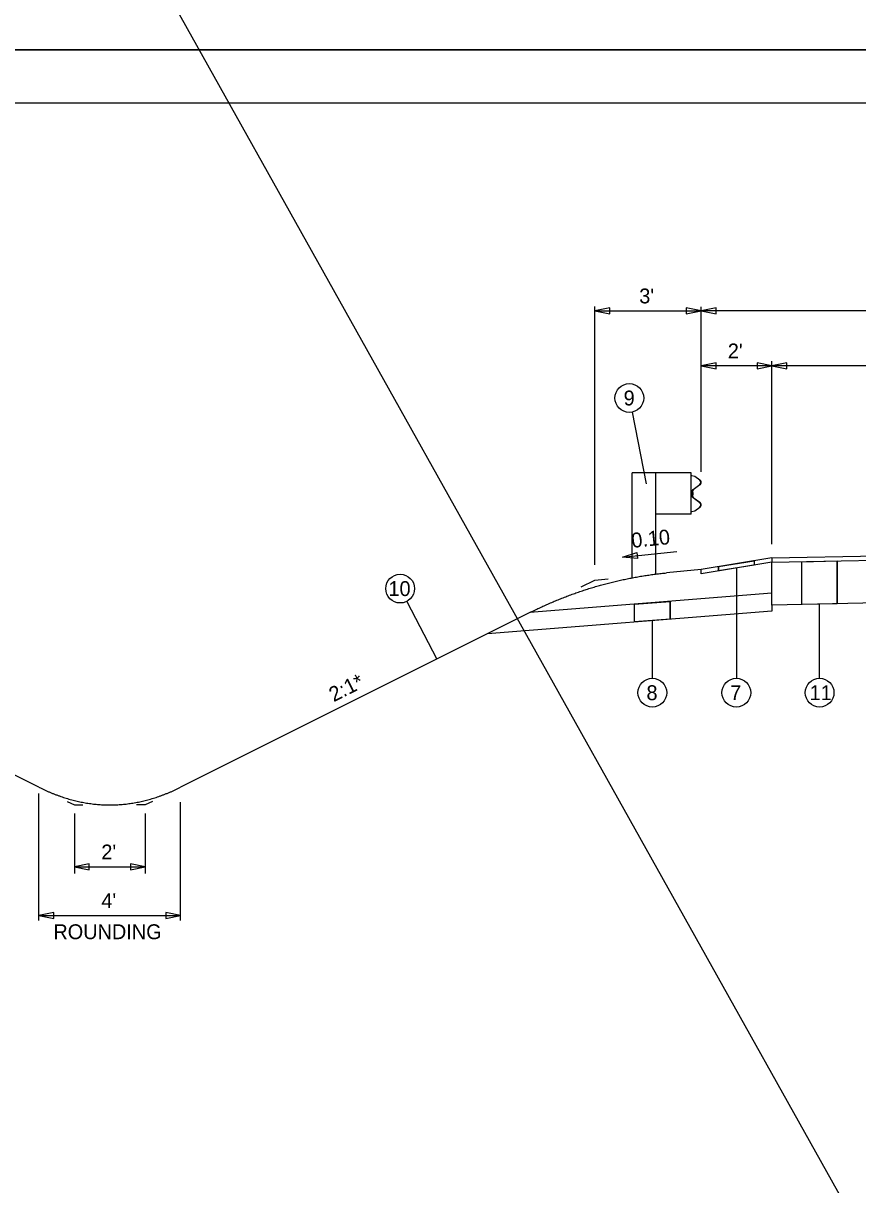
# Model space of a CAD drawing. Extents: x -396 to 156, y -166 to 172.
# Drawn here: x -342.79 to -319.23, y 35.47 to 68.25 of the extents above; entities that cross this region are included whole.
import ezdxf

# ---------------------------------------------------------------- set-up
doc = ezdxf.new("R2010")
doc.units = 0
for name, color, linetype in [('MT_P_Temp_Road', 7, 'Continuous'), ('RD_P_Cells', 7, 'Continuous'), ('SH_Border', 7, 'Continuous'), ('SH_Cut_Line', 7, 'Continuous'), ('TX_P_1', 7, 'Continuous'), ('TX_X_1', 7, 'Continuous'), ('XS_P_Finished_Grade', 7, 'Continuous'), ('XS_P_Pavt_Surface', 7, 'Continuous')]:
    doc.layers.add(name, color=color, linetype=linetype)

msp = doc.modelspace()

# ---------------------------------------------------------------- linework, layer by layer
at = {"layer": 'MT_P_Temp_Road'}
for p, q in [((-321.652, 51.829), (-321.652, 53.037)), ((-318.652, 51.891), (-321.652, 51.829))]:
    msp.add_line(p, q, dxfattribs=at)
at = {"layer": 'RD_P_Cells'}
for p, q in [((-324.933, 55.559), (-325.6, 55.559)), ((-325.6, 52.599), (-325.6, 55.559)), ((-323.933, 55.559), (-324.933, 55.559)), ((-324.933, 52.705), (-324.933, 55.559)), ((-323.933, 54.392), (-323.933, 55.559)), ((-323.918, 55.487), (-323.918, 55.487)), ((-323.918, 55.487), (-323.831, 55.472)), ((-323.918, 55.477), (-323.918, 55.487)), ((-323.918, 55.477), (-323.918, 55.477)), ((-323.835, 55.463), (-323.918, 55.477)), ((-323.835, 55.463), (-323.835, 55.463)), ((-323.693, 55.357), (-323.835, 55.463)), ((-323.831, 55.472), (-323.831, 55.472)), ((-323.831, 55.472), (-323.687, 55.365)), ((-323.813, 55.447), (-323.813, 55.447)), ((-323.807, 55.455), (-323.807, 55.455)), ((-323.881, 55.093), (-323.694, 55.231)), ((-323.881, 55.093), (-323.881, 55.093)), ((-323.688, 55.223), (-323.875, 55.085)), ((-323.814, 55.142), (-323.814, 55.142)), ((-323.808, 55.135), (-323.808, 55.135)), ((-323.694, 55.231), (-323.694, 55.231)), ((-323.693, 55.357), (-323.693, 55.357)), ((-323.688, 55.223), (-323.688, 55.223)), ((-323.687, 55.365), (-323.687, 55.365)), ((-323.662, 55.294), (-323.662, 55.294)), ((-323.652, 55.294), (-323.652, 55.294)), ((-323.917, 55.021), (-323.917, 55.021)), ((-323.917, 54.93), (-323.917, 55.021)), ((-323.917, 54.944), (-323.917, 55.007)), ((-323.917, 54.93), (-323.917, 54.93)), ((-323.907, 55.021), (-323.907, 55.021)), ((-323.907, 55.021), (-323.907, 54.93)), ((-323.907, 54.944), (-323.907, 55.007)), ((-323.907, 54.93), (-323.907, 54.93)), ((-323.881, 54.858), (-323.881, 54.858)), ((-323.693, 54.721), (-323.881, 54.858)), ((-323.875, 55.085), (-323.875, 55.085)), ((-323.875, 54.866), (-323.875, 54.866)), ((-323.875, 54.866), (-323.687, 54.729)), ((-323.916, 54.474), (-323.833, 54.489)), ((-323.829, 54.479), (-323.916, 54.464)), ((-323.916, 54.474), (-323.916, 54.474)), ((-323.916, 54.464), (-323.916, 54.474)), ((-323.916, 54.464), (-323.916, 54.464)), ((-323.833, 54.489), (-323.692, 54.595)), ((-323.686, 54.587), (-323.829, 54.479)), ((-323.693, 54.721), (-323.693, 54.721)), ((-323.692, 54.595), (-323.692, 54.595)), ((-323.687, 54.729), (-323.687, 54.729)), ((-323.686, 54.587), (-323.686, 54.587)), ((-323.661, 54.658), (-323.661, 54.658)), ((-323.651, 54.658), (-323.651, 54.658)), ((-323.933, 54.392), (-324.933, 54.392))]:
    msp.add_line(p, q, dxfattribs=at)
for points in [[(-323.899, 55.036), (-323.899, 54.916), (-323.907, 54.916), (-323.907, 55.036)], [(-323.899, 55.004), (-323.899, 54.946), (-323.874, 54.946), (-323.874, 55.004)]]:
    msp.add_lwpolyline(points, close=True, dxfattribs=at)
for centre, radius, start, end in [((-323.829, 55.022), 0.0886, 126.318, 180.0944), ((-323.741, 55.294), 0.0787, 306.318, 53.2212), ((-323.741, 55.294), 0.0886, 306.318, 53.2212), ((-323.828, 54.93), 0.0886, 180.0944, 233.8707), ((-323.829, 55.022), 0.0788, 126.318, 180.0944), ((-323.828, 54.93), 0.0788, 180.0944, 233.8707), ((-323.739, 54.658), 0.0787, 306.9675, 53.8707), ((-323.739, 54.658), 0.0886, 306.9675, 53.8707)]:
    msp.add_arc(centre, radius, start, end, dxfattribs=at)
at = {"layer": 'SH_Border'}
msp.add_lwpolyline([(-354.402, 66.004), (-258.402, 66.004), (-258.402, 3.004), (-354.402, 3.004)], close=True, dxfattribs=at)
at = {"layer": 'SH_Cut_Line'}
for points in [[(-358.902, 67.504), (-256.902, 67.504), (-256.902, 133.504), (-358.902, 133.504)], [(-358.902, 1.504), (-256.902, 1.504), (-256.902, 67.504), (-358.902, 67.504)]]:
    msp.add_lwpolyline(points, close=True, dxfattribs=at)
at = {"layer": 'TX_P_1'}
for p, q in [((-326.652, 52.968), (-326.652, 60.256)), ((-326.652, 60.136), (-323.652, 60.136)), ((-326.232, 60.052), (-326.232, 60.22)), ((-324.072, 60.22), (-324.072, 60.052)), ((-323.652, 55.588), (-323.652, 60.247)), ((-308.652, 60.136), (-323.652, 60.136)), ((-323.232, 60.052), (-323.232, 60.22)), ((-321.652, 53.553), (-321.652, 58.712)), ((-321.652, 58.583), (-323.652, 58.583)), ((-323.232, 58.499), (-323.232, 58.667)), ((-322.072, 58.667), (-322.072, 58.499)), ((-308.652, 58.583), (-321.652, 58.583)), ((-321.232, 58.499), (-321.232, 58.667)), ((-325.878, 53.186), (-324.343, 53.339)), ((-325.468, 53.311), (-325.452, 53.144)), ((-321.652, 52.164), (-328.493, 51.616)), ((-321.652, 51.829), (-321.652, 51.662)), ((-321.652, 51.662), (-329.688, 51.019)), ((-342.35, 42.924), (-342.35, 46.509)), ((-338.35, 42.924), (-338.35, 46.265)), ((-341.35, 45.95), (-341.35, 44.25)), ((-339.35, 45.95), (-339.35, 44.25)), ((-341.35, 44.44), (-339.35, 44.44)), ((-340.93, 44.356), (-340.93, 44.524)), ((-339.77, 44.524), (-339.77, 44.356)), ((-342.35, 43.064), (-338.35, 43.064)), ((-341.93, 42.98), (-341.93, 43.148)), ((-338.77, 43.148), (-338.77, 42.98))]:
    msp.add_line(p, q, dxfattribs=at)
for points in [[(-326.232, 60.22), (-326.652, 60.136), (-326.232, 60.052)], [(-324.072, 60.052), (-323.652, 60.136), (-324.072, 60.22)], [(-323.232, 60.22), (-323.652, 60.136), (-323.232, 60.052)], [(-323.232, 58.667), (-323.652, 58.583), (-323.232, 58.499)], [(-322.072, 58.499), (-321.652, 58.583), (-322.072, 58.667)], [(-321.232, 58.667), (-321.652, 58.583), (-321.232, 58.499)], [(-325.452, 53.144), (-325.878, 53.186), (-325.468, 53.311)], [(-327.042, 52.342), (-326.652, 52.537), (-326.277, 52.575)], [(-341.553, 46.289), (-341.35, 46.188), (-341.108, 46.188)], [(-339.148, 46.289), (-339.35, 46.188), (-339.593, 46.188)], [(-340.93, 44.524), (-341.35, 44.44), (-340.93, 44.356)], [(-339.77, 44.356), (-339.35, 44.44), (-339.77, 44.524)], [(-341.93, 43.148), (-342.35, 43.064), (-341.93, 42.98)], [(-338.77, 42.98), (-338.35, 43.064), (-338.77, 43.148)]]:
    msp.add_lwpolyline(points, dxfattribs=at)
for points in [[(-323.158, 52.792), (-323.158, 52.917), (-322.158, 53.08), (-322.158, 52.955)], [(-324.53, 51.933), (-324.53, 51.432), (-325.53, 51.352), (-325.53, 51.853)]]:
    msp.add_lwpolyline(points, close=True, dxfattribs=at)
for centre in [(-325.68, 57.675), (-332.153, 52.295), (-325.03, 49.356), (-322.658, 49.356), (-320.308, 49.356)]:
    msp.add_circle(centre, 0.406, dxfattribs=at)
at = {"layer": 'TX_X_1'}
for p, q in [((-325.602, 57.276), (-325.209, 55.253)), ((-323.158, 52.917), (-323.158, 52.792)), ((-322.658, 52.874), (-322.658, 49.762)), ((-322.158, 53.08), (-322.158, 52.955)), ((-320.808, 51.846), (-320.808, 53.055)), ((-319.808, 51.867), (-319.808, 53.075)), ((-331.965, 51.935), (-331.113, 50.307)), ((-325.53, 51.352), (-325.53, 51.853)), ((-324.53, 51.432), (-324.53, 51.933)), ((-320.308, 49.762), (-320.308, 51.857)), ((-325.03, 49.762), (-325.03, 51.392))]:
    msp.add_line(p, q, dxfattribs=at)
msp.add_lwpolyline([(-320.808, 51.846), (-320.808, 53.055), (-319.808, 53.075), (-319.808, 51.867)], close=True, dxfattribs=at)
at = {"layer": 'XS_P_Finished_Grade'}
for p, q in [((-396.097, 171.685), (-207.077, -166.247)), ((-323.652, 52.837), (-324.628, 52.739)), ((-328.471, 51.628), (-338.35, 46.688)), ((-342.35, 46.688), (-344.594, 47.809))]:
    msp.add_line(p, q, dxfattribs=at)
for points in [[(-328.471, 51.628), (-328.401, 51.662), (-328.331, 51.697), (-328.26, 51.73), (-328.19, 51.763), (-328.119, 51.796), (-328.048, 51.828), (-327.977, 51.86), (-327.906, 51.891), (-327.835, 51.921), (-327.764, 51.951), (-327.692, 51.981), (-327.62, 52.01), (-327.549, 52.038), (-327.477, 52.066), (-327.404, 52.093), (-327.332, 52.12), (-327.26, 52.147), (-327.187, 52.172), (-327.114, 52.198), (-327.041, 52.223), (-326.968, 52.247), (-326.895, 52.271), (-326.822, 52.294), (-326.748, 52.316), (-326.675, 52.339), (-326.601, 52.36), (-326.527, 52.381), (-326.453, 52.402), (-326.378, 52.422), (-326.304, 52.442), (-326.229, 52.461), (-326.155, 52.479), (-326.08, 52.497), (-326.005, 52.515), (-325.93, 52.532), (-325.854, 52.548), (-325.779, 52.564), (-325.703, 52.579), (-325.627, 52.594), (-325.551, 52.608), (-325.475, 52.622), (-325.399, 52.635), (-325.323, 52.648), (-325.246, 52.66), (-325.17, 52.672), (-325.093, 52.683), (-325.016, 52.694), (-324.939, 52.704), (-324.861, 52.714), (-324.784, 52.723), (-324.706, 52.731), (-324.628, 52.739)], [(-342.35, 46.688), (-342.273, 46.65), (-342.197, 46.614), (-342.12, 46.579), (-342.043, 46.546), (-341.966, 46.514), (-341.889, 46.484), (-341.812, 46.455), (-341.735, 46.427), (-341.658, 46.402), (-341.581, 46.377), (-341.504, 46.354), (-341.427, 46.333), (-341.35, 46.313), (-341.273, 46.294), (-341.197, 46.277), (-341.12, 46.262), (-341.043, 46.248), (-340.966, 46.235), (-340.889, 46.224), (-340.812, 46.214), (-340.735, 46.206), (-340.658, 46.2), (-340.581, 46.194), (-340.504, 46.191), (-340.427, 46.189), (-340.35, 46.188), (-340.273, 46.189), (-340.197, 46.191), (-340.12, 46.194), (-340.043, 46.2), (-339.966, 46.206), (-339.889, 46.214), (-339.812, 46.224), (-339.735, 46.235), (-339.658, 46.248), (-339.581, 46.262), (-339.504, 46.277), (-339.427, 46.294), (-339.35, 46.313), (-339.273, 46.333), (-339.197, 46.354), (-339.12, 46.377), (-339.043, 46.402), (-338.966, 46.427), (-338.889, 46.455), (-338.812, 46.484), (-338.735, 46.514), (-338.658, 46.546), (-338.581, 46.579), (-338.504, 46.614), (-338.427, 46.65), (-338.35, 46.688)]]:
    msp.add_spline(points, degree=3, dxfattribs=at)
at = {"layer": 'XS_P_Pavt_Surface'}
for p, q in [((-321.652, 53.162), (-323.652, 52.837)), ((-321.652, 53.162), (-321.652, 53.037)), ((-321.652, 53.037), (-323.652, 52.712)), ((-323.652, 52.712), (-323.652, 52.837))]:
    msp.add_line(p, q, dxfattribs=at)
for points in [[(-321.652, 53.162), (-318.652, 53.224), (-316.75, 53.264), (-308.705, 53.471), (-305.413, 53.376), (-298.652, 53.107)], [(-321.652, 53.037), (-316.75, 53.139), (-308.705, 53.346), (-305.413, 53.251), (-297.652, 52.942)]]:
    msp.add_lwpolyline(points, dxfattribs=at)

# ---------------------------------------------------------------- texts
at = {"layer": 'TX_P_1'}
for s, p in [("3'", (-325.4, 60.346)), ("2'", (-322.9, 58.793)), ('9', (-325.841, 57.465)), ('10', (-332.482, 52.085)), ('8', (-325.196, 49.146)), ('7', (-322.833, 49.146)), ('11', (-320.59, 49.146)), ("2'", (-340.589, 44.65)), ("4'", (-340.589, 43.274)), ('ROUNDING', (-341.944, 42.398))]:
    msp.add_text(s, height=0.42, dxfattribs=at).set_placement(p)
msp.add_text('2:1*', height=0.42, rotation=26.5651, dxfattribs=at).set_placement((-334.028, 49.084))
at = {"layer": 'XS_P_Finished_Grade'}
msp.add_text('0.10', height=0.42, rotation=5.7106, dxfattribs=at).set_placement((-325.602, 53.444))

doc.saveas('drawing.dxf')
